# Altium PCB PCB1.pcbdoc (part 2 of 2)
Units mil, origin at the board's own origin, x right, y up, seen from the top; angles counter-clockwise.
Board outline 3120 x 2755.91 mil, 2 copper layers (Top Layer, Bottom Layer), stack 62.205 mil thick; 41 components, 124 nets, 614 pads, 395 vias.
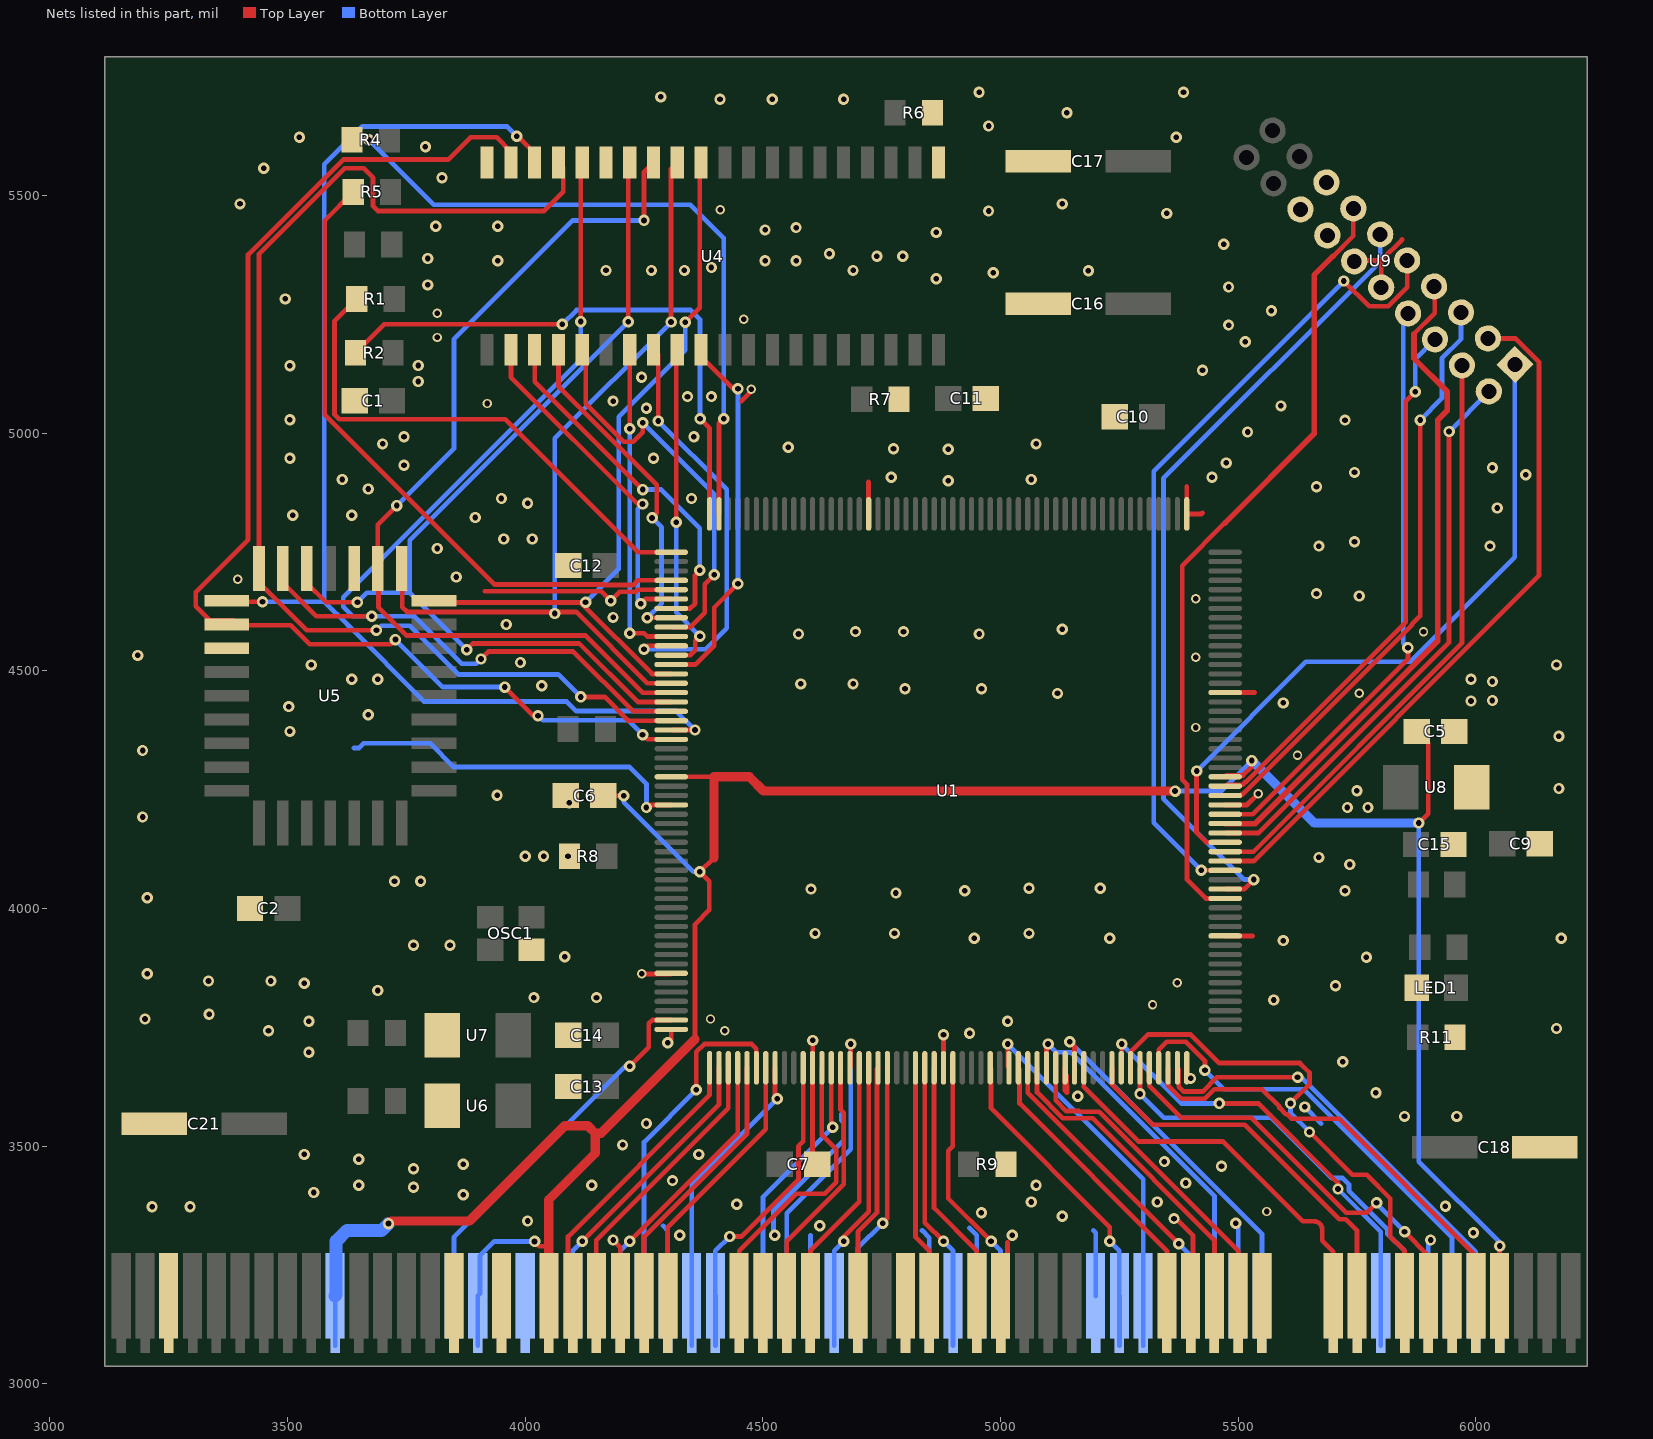
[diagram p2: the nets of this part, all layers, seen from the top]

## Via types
v1: diameter 23.62, hole 11.81, Top Layer to Bottom Layer, 223 vias
v2: diameter 24.02, hole 12.01, Top Layer to Bottom Layer, 148 vias
v3: diameter 19.68, hole 11.81, Top Layer to Bottom Layer, 20 vias
v4: diameter 23.62, hole 12.01, Top Layer to Bottom Layer, 3 vias
v5: diameter 39.37, hole 19.68, Top Layer to Bottom Layer, 1 vias

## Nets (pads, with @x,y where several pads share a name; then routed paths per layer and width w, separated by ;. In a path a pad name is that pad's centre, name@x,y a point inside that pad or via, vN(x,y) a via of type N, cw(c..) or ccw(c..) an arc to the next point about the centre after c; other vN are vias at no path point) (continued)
CASAL: R5.2 U1.160 | length 1375.1
  Top Layer w9.92: R5.2@3638.13,5507.68 3578.13,5447.68 3578.13,5039.47 3935.83,4681.77 4165.84,4681.77 4167.02,4680.59 4227.02,4680.59 4237.02,4690.59 U1.160@4307.32,4690.59
D0: U1.162 U4.2 | length 730.3
  Top Layer w9.92: U4.2@3970,5175.83 3970,5118.23 4237.02,4851.22 v2(4247.01,4851.22)
  Top Layer w10.24: v2(4242.96,4641.22) 4252.96,4651.22 U1.162@4307.32,4651.22
  Bottom Layer w9.92: v2(4242.96,4641.22) 4237.02,4647.16 4237.02,4841.22 v2(4247.01,4851.22)
D1: U1.163 U4.3 | length 759.2
  Top Layer w9.92: U4.3@4020,5175.83 4020,5108.86 v2(4247.33,4881.54) ; U1.163@4307.32,4631.54 4347.32,4631.54 4357.32,4641.54 4357.32,4701.54 v2(4367.32,4711.54)
  Bottom Layer w9.92: v2(4247.33,4881.54) 4286.14,4881.54 4367.32,4800.35 v2(4367.32,4711.54)
D2: U1.164 U4.4 | length 724.9
  Top Layer w9.92: U4.4@4070,5175.83 4070,5098.86 4277.01,4891.85 4277.01,4831.85 v2(4267.01,4821.85) ; v2(4257.01,4611.85) U1.164@4307.32,4611.85
  Bottom Layer w9.92: v2(4257.01,4611.85) 4287.01,4641.85 4287.01,4801.85 v2(4267.01,4821.85)
D3: U1.165 U4.5 | length 851.4
  Top Layer w9.92: U4.5@4120,5175.83 4127.64,5168.19 4127.64,5062.17 4207.64,4982.17 4227.64,4982.17 4247.64,5002.17 v2(4247.64,5022.17) ; U1.165@4307.32,4592.17 4347.64,4592.17 4377.64,4622.17 4377.64,4682.17 v2(4397.63,4702.17)
  Bottom Layer w9.92: v2(4247.64,5022.17) 4397.63,4872.17 v2(4397.63,4702.17)
D4: U1.166 U4.7 | length 686.6
  Top Layer w9.92: v2(4220,4579.49) 4250,4579.49 4257.01,4572.48 U1.166@4307.32,4572.48 ; v2(4220,5009.49) U4.7@4220,5175.83
  Bottom Layer w9.92: v2(4220,4579.49) v2(4220,5009.49)
D5: U1.167 U4.8 | length 902.3
  Top Layer w9.92: v2(4250,4545.79) 4257.01,4552.8 U1.167@4307.32,4552.8 ; U4.8@4270,5175.83 4280,5165.82 v2(4280,5025.78)
  Bottom Layer w9.92: v2(4250,4545.79) 4380,4545.79 4423.98,4589.76 4423.98,4881.81 v2(4280,5025.78)
D6: U1.168 U4.9 | length 713
  Top Layer w9.92: U1.168@4307.32,4533.11 4347.64,4533.11 4357.64,4543.11 4357.64,4563.11 v2(4367.64,4573.11) ; v2(4317.64,4813.11) 4317.64,5173.46 U4.9@4320,5175.83
  Bottom Layer w9.92: v2(4317.64,4813.11) 4317.64,4623.11 v2(4367.64,4573.11)
D7: U1.169 U4.10 | length 788
  Top Layer w9.92: U1.169@4307.32,4513.43 4357.64,4513.43 4397.63,4553.43 4397.63,4633.43 v2(4447.63,4683.43) ; U4.10@4370,5175.83 4377.64,5168.19 4377.64,5153.43 4437.63,5093.43 v2(4447.63,5093.43)
  Bottom Layer w9.92: v2(4447.63,4683.43) v2(4447.63,5093.43)
D8: U1.170 U4.31 U5.13 | length 1599.1
  Top Layer w9.92: U5.13@3807.92,4647.68 3811.86,4643.74 v2@4117.02,4643.74 ; v2(4127.02,4644.57) 4117.85,4644.57 v2@4117.02,4643.74 ; U1.170@4307.32,4493.74 4267.01,4493.74 v2@4117.02,4643.74 ; v2(4337.01,5233.73) 4367.01,5263.73 4367.01,5566.54 U4.31@4370,5569.53
  Bottom Layer w9.92: v2(4127.02,4644.57) 4197.02,4714.57 4197.02,5034.69 4337.01,5174.69 v2(4337.01,5233.73)
D9: U1.171 U4.32 U5.14 | length 1774.4
  Top Layer w9.92: U5.14@3740,4715.59 3741.53,4714.06 3741.53,4634.06 3751.53,4624.06 v2@4065.44,4624.06 ; v2@4067.02,4624.06 4107.02,4624.06 4257.01,4474.06 U1.171@4307.32,4474.06
  Top Layer w10: v2(4062.17,4620.78) 4065.44,4624.06 v2@4067.02,4624.06 ; v2(4307.01,5234.06) 4307.01,5556.54 U4.32@4320,5569.53
  Bottom Layer w10: v2(4062.17,4620.78) 4062.17,4989.21 v2(4307.01,5234.06)
D10: U1.172 U4.33 U5.15 | length 1954.4
  Top Layer w9.92: U5.15@3690,4715.59 3691.22,4714.37 3691.22,4634.37 3751.22,4574.37 4127.02,4574.37 4247.01,4454.37 U1.172@4307.32,4454.37
  Top Layer w10: U5.15@3690,4715.59 3690,4807.84 v2(3730,4847.84) ; v2(4249.99,5447.84) 4249.99,5549.52 U4.33@4270,5569.53
  Bottom Layer w10: v2(3730,4847.84) 3850,4967.84 3850,5197.84 4099.99,5447.84 v2(4249.99,5447.84)
D11: U1.173 U4.34 U5.18 | length 2025.2
  Top Layer w9.92: U5.18@3540,4715.59 3540.9,4714.69 3540.9,4684.69 3580.9,4644.69 v2(3647.02,4644.69) ; v2(3877.02,4544.69) 3890,4557.68 4114.03,4557.68 4237.02,4434.69 U1.173@4307.32,4434.69
  Top Layer w10: v2(4217.02,5234.69) 4217.02,5566.54 U4.34@4220,5569.53
  Bottom Layer w9.92: v2(3647.02,4644.69) 3667.02,4664.69 3757.02,4664.69 3765.66,4656.04 v2(3877.02,4544.69)
  Bottom Layer w10: 3757.02,4664.69 3757.02,4774.69 v2(4217.02,5234.69)
D12: U1.174 U4.36 U5.19 | length 2191.9
  Top Layer w9.92: U5.19@3490,4715.59 3490.59,4715 3490.59,4685 3560.59,4615 v2(3677.02,4615) ; v2(3907.02,4525) 3922.77,4540.75 4101.26,4540.75 4227.02,4415 U1.174@4307.32,4415
  Top Layer w10: v2(4117.02,5234.99) 4117.02,5566.54 U4.36@4120,5569.53
  Bottom Layer w9.92: v2(3677.02,4615) 3767.02,4615 3867.02,4515 3897.02,4515 v2(3907.02,4525)
  Bottom Layer w10: v2(3677.02,4615) 3637.02,4615 3617.02,4635 3617.02,4655 4117.02,5154.99 v2(4117.02,5234.99)
D13: U1.175 U4.37 U5.20 | length 2557.1
  Top Layer w9.92: U5.20@3440.27,4715.32 3440.27,4685.32 3540.27,4585.32 v2(3687.02,4585.32) ; v2(4117.02,4445.32) 4167.02,4445.32 4217.02,4395.32 U1.175@4307.32,4395.32
  Top Layer w10: U5.20@3440,4715.59 3440,5377.84 3620,5557.84 3660,5557.84 3680,5537.84 3680,5477.84 3690,5467.84 4039.99,5467.84 4079.99,5507.84 4079.99,5559.53 U4.37@4070,5569.53
  Bottom Layer w9.92: v2(3687.02,4585.32) 3697.02,4595.32 3757.02,4595.32 3859.66,4492.68 4069.66,4492.68 v2(4117.02,4445.32)
D14: U1.176 U4.38 U5.21 | length 2587
  Top Layer w9.92: U5.21@3372.09,4647.68 3374.14,4645.63 v2(3447.33,4645.63) ; U1.176@4307.32,4375.63 v2(4357.32,4375.63)
  Top Layer w10: v2(3982.33,5625) 3984.53,5625 4017.33,5592.2 4017.33,5572.2 U4.38@4020,5569.53
  Bottom Layer w9.92: v2(3447.33,4645.63) 3577.33,4645.63 3627.33,4595.63 3787.33,4435.63 4087.33,4435.63 4107.33,4415.63 4317.32,4415.63 v2(4357.32,4375.63)
  Bottom Layer w10: 3577.33,4645.63 3577.33,5565.62 3657.33,5645.62 3961.7,5645.62 v2(3982.33,5625)
D15: U1.177 U4.39 U5.22 | length 2619.3
  Top Layer w9.92: U5.22@3372.09,4597.68 3380.35,4605.95 3387.02,4605.95 3397.02,4595.95 3507.02,4595.95 3547.02,4555.95 3717.02,4555.95 v2(3727.02,4565.95) ; v2(3957.02,4465.95) 4017.02,4405.95 v2(4027.02,4405.95) ; v2(4247.01,4365.95) 4257.01,4355.95 U1.177@4307.32,4355.95
  Top Layer w10: U5.22@3387.02,4605.95 3337.02,4605.95 3307.02,4635.95 3307.02,4665.95 3417.02,4775.95 3417.02,5375.95 3617.02,5575.95 3838.27,5575.95 3885,5622.68 3940,5622.68 3970,5592.67 U4.39@3970,5569.53
  Bottom Layer w9.92: v2(3727.02,4565.95) 3827.02,4465.95 v2(3957.02,4465.95) ; v2(4027.02,4405.95) 4037.02,4395.95 4217.02,4395.95 v2(4247.01,4365.95)
DD0: ?.A58 U1.51 | length 1032.2
  Top Layer w9.92: U1.51@5372.28,3665 5375.15,3662.13 5375.15,3625 5385.15,3615 5425.15,3615 5455.15,3645 v2(5625.15,3645)
  Bottom Layer w9.92: v2(5625.15,3645) 5632.68,3645 6000.2,3277.48 ?.A58@6000.19,3185.04
  Bottom Layer w10: ?.A58@6000.19,3080.31 ?.A58@6000.19,3185.04
DD1: ?.B58 U1.50 | length 1040.8
  Top Layer w9.92: U1.50@5352.6,3665 5352.6,3627.55 5380.2,3599.96 5430.2,3599.96 5450.2,3619.96 5550.2,3619.96 5587.24,3582.91 5587.24,3580.45 5600.69,3567.01 5603.15,3567.01 5612.48,3557.68 5712.48,3557.68 6000.2,3269.96 ?.B58@6000.19,3185.04
  Top Layer w10: ?.B58@6000.19,3080.31 ?.B58@6000.19,3185.04
DD2: ?.A57 U1.49 | length 1071.9
  Top Layer w9.92: U1.49@5332.91,3665 5332.91,3702.67 5350.2,3719.96 5390.2,3719.96 5430.2,3679.96 v2(5430.2,3659.96)
  Bottom Layer w9.92: v2(5430.2,3659.96) 5470.2,3619.96 5637.72,3619.96 5950.2,3307.48 ?.A57@5950.19,3185.04
  Bottom Layer w10: ?.A57@5950.19,3080.31 ?.A57@5950.19,3185.04
DD3: ?.B56 U1.48 | length 981.3
  Top Layer w9.92: U1.48@5313.23,3665 5313.23,3626.92 5380.2,3559.96 5527.72,3559.96 5727.72,3359.96 5770.2,3359.96 v2(5791.27,3381.04) ; v2(5850.2,3319.96) 5900.2,3269.96 ?.B56@5900.19,3185.04
  Top Layer w10: ?.B56@5900.19,3080.31 ?.B56@5900.19,3185.04
  Bottom Layer w9.92: v2(5791.27,3381.04) 5791.27,3378.88 v2(5850.2,3319.96)
DD4: ?.A55 U1.47 | length 961.2
  Top Layer w9.92: v2(5293.54,3609.96) U1.47@5293.54,3665
  Bottom Layer w9.92: v2(5293.54,3609.96) 5343.54,3559.96 5570.2,3559.96 5697.25,3432.9 5719.69,3432.9 5733.14,3419.46 5733.14,3406.71 5814.13,3325.71 5814.13,3316.02 5850.2,3279.96 ?.A55@5850.19,3185.04
  Bottom Layer w10: ?.A55@5850.19,3080.31 ?.A55@5850.19,3185.04
DD5: ?.B55 U1.46 | length 1166.4
  Top Layer w9.92: U1.46@5273.86,3665 5273.86,3698.67 5310.2,3735 5400.2,3735 5460.2,3675 5630.2,3675 5650.2,3655 5650.2,3629.96 v2(5610.2,3589.96) ; v2(5650.2,3529.96) 5740.2,3439.96 5770.2,3439.96 5820.2,3389.96 5820.2,3309.96 5850.2,3279.96 ?.B55@5850.19,3185.04
  Top Layer w10: ?.B55@5850.19,3080.31 ?.B55@5850.19,3185.04
  Bottom Layer w9.92: v2(5610.2,3589.96) 5610.2,3569.96 v2(5650.2,3529.96)
DD6: ?.A54 U1.45 | length 1006.1
  Top Layer w9.92: U1.45@5254.17,3665 5255.15,3665.99 v2(5255.15,3715) ; v2(5460.2,3589.96) 5542.72,3589.96 5710.19,3422.49 v2(5710.19,3409.95)
  Bottom Layer w9.92: v2(5255.15,3715) 5380.2,3589.96 v2(5460.2,3589.96) ; v2(5710.19,3409.95) 5800.2,3319.94 ?.A54@5800.19,3185.04
  Bottom Layer w10: ?.A54@5800.19,3080.31 ?.A54@5800.19,3185.04
DD7: ?.B53 U1.44 | length 919.8
  Top Layer w9.92: U1.44@5234.49,3665 5234.49,3630.74 5320.2,3545.04 5513.61,3545.04 5712.62,3346.02 5726.66,3346.02 5750.2,3322.48 ?.B53@5750.19,3185.04
  Top Layer w10: ?.B53@5750.19,3080.31 ?.B53@5750.19,3185.04
DD8: ?.B52 U1.41 | length 922.9
  Top Layer w9.92: U1.41@5175.43,3665 5175.43,3624.73 5290.2,3509.96 5467.72,3509.96 5635.71,3341.97 5660.04,3341.97 cw(c5660.04,3325.2) 5676.81,3325.2 5676.81,3300.87 5700.2,3277.48 ?.B52@5700.19,3185.04 ?.B52@5700.19,3080.31
DD9: ?.A49 U1.40 | length 866.3
  Top Layer w9.92: v2(5145.75,3719.96) 5155.75,3709.96 U1.40@5155.75,3665
  Bottom Layer w9.92: v2(5145.75,3719.96) 5550.2,3315.51 ?.A49@5550.2,3185.04
  Bottom Layer w10: ?.A49@5550.2,3080.31 ?.A49@5550.2,3185.04
DD10: ?.B48 U1.38 | length 783.2
  Top Layer w9.92: U1.38@5116.38,3665 5116.38,3596.29 5138.78,3573.9 5165.97,3573.9 5167.19,3572.68 5207.48,3572.68 5500.2,3279.96 ?.B48@5500.2,3185.04
  Top Layer w10: ?.B48@5500.2,3080.31 ?.B48@5500.2,3185.04
DD11: ?.A47 U1.37 | length 849.2
  Top Layer w9.92: U1.37@5096.69,3665 5096.69,3711.49 v2(5100.2,3715)
  Bottom Layer w9.92: v2(5100.2,3715) 5117.52,3697.68 5135.57,3697.68 5136.24,3697.01 5149,3697.01 5450.2,3395.8 ?.A47@5450.2,3185.04
  Bottom Layer w10: ?.A47@5450.2,3080.31 ?.A47@5450.2,3185.04
DD12: ?.B47 U1.36 | length 775.9
  Top Layer w9.92: U1.36@5077.01,3665 5077.01,3613.14 5131.42,3558.74 5193.94,3558.74 5450.2,3302.48 ?.B47@5450.2,3185.04
  Top Layer w10: ?.B47@5450.2,3080.31 ?.B47@5450.2,3185.04
DD13: ?.A46 U1.35 | length 726.7
  Top Layer w9.92: U1.35@5057.32,3665 5057.32,3612.84 v2(5375.2,3294.96)
  Bottom Layer w9.92: v2(5375.2,3294.96) 5400.2,3269.96 ?.A46@5400.2,3185.04
  Bottom Layer w10: ?.A46@5400.2,3080.31 ?.A46@5400.2,3185.04
DD14: ?.B45 U1.34 | length 714.2
  Top Layer w9.92: U1.34@5037.64,3665 5040.2,3662.45 5040.2,3589.96 5350.2,3279.96 ?.B45@5350.2,3185.04
  Top Layer w10: ?.B45@5350.2,3080.31 ?.B45@5350.2,3185.04
DD15: ?.A44 U1.33 | length 803.8
  Top Layer w9.92: v2(5015.24,3715) 5015.24,3667.71 U1.33@5017.95,3665
  Bottom Layer w9.92: v2(5015.24,3715) 5300.2,3430.04 ?.A44@5300.2,3185.04
  Bottom Layer w10: ?.A44@5300.2,3080.31 ?.A44@5300.2,3185.04
DD16: ?.A32 U1.20 | length 610.3
  Top Layer w9.92: v2(4752.05,3338.1) 4762.05,3348.1 U1.20@4762.05,3665
  Bottom Layer w9.92: ?.A32@4700.2,3185.04 4700.2,3286.25 v2(4752.05,3338.1)
  Bottom Layer w10: ?.A32@4700.2,3080.31 ?.A32@4700.2,3185.04
DD17: ?.B32 U1.19 | length 602.2
  Top Layer w9.92: ?.B32@4700.2,3185.04 4700.2,3319.96 4740.2,3359.96 4740.2,3662.84 U1.19@4742.36,3665
  Top Layer w10: ?.B32@4700.2,3080.31 ?.B32@4700.2,3185.04
DD18: ?.A31 U1.18 | length 614.7
  Top Layer w9.92: v2(4670.2,3299.96) 4670.2,3309.96 4722.68,3362.44 U1.18@4722.68,3665
  Bottom Layer w9.92: ?.A31@4650.2,3185.04 4650.2,3279.96 v2(4670.2,3299.96)
  Bottom Layer w10: ?.A31@4650.2,3080.31 ?.A31@4650.2,3185.04
DD19: ?.B30 U1.17 | length 627.3
  Top Layer w9.92: ?.B30@4600.2,3185.04 4600.2,3279.96 4702.99,3382.75 U1.17@4702.99,3665
  Top Layer w10: ?.B30@4600.2,3080.31 ?.B30@4600.2,3185.04
DD20: ?.A29 U1.16 | length 741.4
  Top Layer w9.92: U1.16@4683.31,3665 4685.16,3666.84 v2(4685.16,3715)
  Bottom Layer w9.92: ?.A29@4550.2,3185.04 4550.2,3358.7 4685.16,3493.66 v2(4685.16,3715)
  Bottom Layer w10: ?.A29@4550.2,3080.31 ?.A29@4550.2,3185.04
DD21: ?.B29 U1.15 | length 637.1
  Top Layer w9.92: ?.B29@4550.2,3185.04 4550.2,3299.96 4670.2,3419.96 4670.2,3569.96 4663.62,3576.54 U1.15@4663.62,3665
  Top Layer w10: ?.B29@4550.2,3080.31 ?.B29@4550.2,3185.04
DD22: ?.A28 U1.14 | length 646.9
  Top Layer w9.92: U1.14@4643.94,3665 4643.94,3543.22 v2(4647.2,3539.96)
  Bottom Layer w9.92: ?.A28@4500.2,3185.04 4500.2,3392.95 v2(4647.2,3539.96)
  Bottom Layer w10: ?.A28@4500.2,3080.31 ?.A28@4500.2,3185.04
DD23: ?.B27 U1.13 | length 716.8
  Top Layer w9.92: ?.B27@4450.2,3185.04 4450.2,3279.96 4570.2,3399.96 4630.2,3399.96 4654.25,3424.01 4654.25,3494.01 4624.25,3524.01 U1.13@4624.25,3665
  Top Layer w10: ?.B27@4450.2,3080.31 ?.B27@4450.2,3185.04
DD24: ?.A25 U1.8 | length 661.1
  Top Layer w9.92: U1.8@4525.83,3665 4525.83,3604.32 v2(4530.2,3599.96)
  Bottom Layer w9.92: ?.A25@4350.2,3185.04 4350.2,3419.96 v2(4530.2,3599.96)
  Bottom Layer w10: ?.A25@4350.2,3080.31 ?.A25@4350.2,3185.04
DD25: ?.B24 U1.7 | length 670
  Top Layer w9.92: ?.B24@4300.2,3185.04 4300.2,3329.96 4506.14,3535.9 U1.7@4506.14,3665
  Top Layer w10: ?.B24@4300.2,3080.31 ?.B24@4300.2,3185.04
DD26: ?.A23 U1.6 | length 841.1
  Top Layer w9.92: v2(4360.2,3618.74) 4360.2,3698.74 4376.46,3715 4476.46,3715 4486.46,3705 U1.6@4486.46,3665
  Bottom Layer w9.92: ?.A23@4250.2,3185.04 4250.2,3508.74 v2(4360.2,3618.74)
  Bottom Layer w10: ?.A23@4250.2,3080.31 ?.A23@4250.2,3185.04
DD27: ?.B23 U1.5 | length 674.4
  Top Layer w9.92: ?.B23@4250.2,3185.04 4250.2,3309.96 4466.77,3526.53 U1.5@4466.77,3665
  Top Layer w10: ?.B23@4250.2,3080.31 ?.B23@4250.2,3185.04
DD28: ?.A22 U1.4 | length 687
  Top Layer w9.92: v2(4220.2,3299.96) 4447.09,3526.85 U1.4@4447.09,3665
  Bottom Layer w9.92: ?.A22@4200.2,3185.04 4200.2,3279.96 v2(4220.2,3299.96)
  Bottom Layer w10: ?.A22@4200.2,3080.31 ?.A22@4200.2,3185.04
DD29: ?.B21 U1.3 | length 699.7
  Top Layer w9.92: ?.B21@4149.8,3185.04 4149.81,3302.48 4427.4,3580.08 U1.3@4427.4,3665
  Top Layer w10: ?.B21@4149.8,3080.31 ?.B21@4149.8,3185.04
DD30: ?.A20 U1.2 | length 712.1
  Top Layer w9.92: v2(4120.2,3299.96) 4407.72,3587.48 U1.2@4407.72,3665
  Bottom Layer w9.92: ?.A20@4100.2,3185.04 4100.2,3279.96 v2(4120.2,3299.96)
  Bottom Layer w10: ?.A20@4100.2,3080.31 ?.A20@4100.2,3185.04
DD31: ?.B20 U1.1 | length 712.2
  Top Layer w9.92: ?.B20@4100.2,3185.04 4090.2,3195.04 4090.2,3309.96 4388.03,3607.79 U1.1@4388.03,3665
  Top Layer w10: ?.B20@4100.2,3080.31 ?.B20@4100.2,3185.04
FLM: U1.67 U9.13 | length 1661.9
  Top Layer w9.84: 5700,5372.68 5742.39,5415.06 U9.13@5742.39,5473.04
  Top Layer w9.92: 5472.37,4811.29 5382.37,4721.29 5382.37,4271.3 5392.37,4261.3 5392.37,4061.3 5432.37,4021.3 U1.67@5472.68,4021.3
  Top Layer w11.81: 5472.37,4811.29 5660,4998.93 5660,5332.68 5700,5372.68
GND: ?.A18 ?.A24 ?.A30 ?.A35 ?.A37 ?.A42 ?.A48 ?.A56 ?.B3 ?.B15 ?.B17 ?.B22 ?.B28 ?.B34 ?.B38 ?.B46 ?.B49 ?.B57 C1.1 C2.1 C5.1 C6.1 C7.1 C9.1 C10.1 C11.1 C12.1 C13.1 C14.1 C15.1 C16.2 C17.2 C18.2 C21.2 LED1.2 OSC1.2 R6.2 R7.2 R8.2 R9.2 R11.1 U1.12 U1.26 U1.39 U1.52 U1.63 U1.77 U1.89 U1.105 U1.139 U1.161 U1.184 U1.202 U1.208 U4.21 U4.35 U4.40 U5.16 U5.23 U6.2 U7.2 U8.2 U9.10 U9.12 U9.14 U9.15 U9.16 | length 4042.2
  Top Layer w9.92: v1(4185,3302.68) 4200.2,3287.48 ?.B22@4200.2,3185.04 ; 4455,5067.68 4475.47,5088.15 v3(4475.47,5092.68) ; ?.B38@5000.2,3185.04 5015,3199.84 5015,3297.68 ; v1(5365,3347.68) 5370,3347.68 5405,3312.68 5405,3189.84 ?.B46@5400.2,3185.04 ; U9.12@5744.33,5361.71 5746.27,5363.65 5800.97,5363.65 ; U9.10@5800.97,5307.01 5800.97,5363.65 ; 5845,5407.68 5800.97,5363.65
  Top Layer w10.24: 3915,4667.68 4160,4667.68 v1(4180,4647.68) 4198.81,4666.49 4232.85,4666.49 4237.27,4670.91 U1.161@4307.32,4670.91 ; v3(4245,3862.68) 4306.18,3862.68 U1.202@4307.32,3863.82 ; v1(4255,4212.68) 4260.47,4218.15 U1.184@4307.32,4218.15 ; v1(4300,3717.68) 4307.32,3725 U1.208@4307.32,3745.71 ; v1@4605,3723.34 v1(4605,3722.68) 4605,3665.43 U1.12@4604.57,3665 4604.57,3471.52 C7.1@4614.26,3461.83 ; U1.139@4722.68,4830.35 4722.68,4897.68 ; U1.26@4880.16,3665 v1(4880.16,3734.27) ; U1.39@5136.06,3665 U1.39@5136.06,3651.57 ; 5391.97,4887.68 U1.105@5391.97,4830.35 5422.68,4830.35 5425,4832.68 ; U1.63@5472.68,3942.56 5530,3942.56 ; U1.77@5472.68,4218.15 5518.65,4218.15 v3(5542.27,4241.77) ; U1.89@5472.68,4454.37 5535,4454.37 ; U1.39@5136.06,3651.57 5139.14,3648.49 5139.14,3628.2 5140,3627.33 5140,3612.68 5136.06,3616.62 U1.39@5136.06,3651.57
  Bottom Layer w9.92: 4290,3332.68 4300.2,3322.48 ?.A24@4300.2,3185.04 ; v1(4525,3312.68) 4522.5,3315.18 4522.5,3365.18 4670,3512.68 4670,3530.3 4670.16,3530.45 4670.16,3549.47 4665,3554.62 4665,3567.68 ; ?.A30@4600.2,3185.04 4600.2,3312.68 ; 4835,3322.68 4850.2,3307.48 ?.A35@4850.2,3185.04 ; 4935,3327.68 4950.2,3312.48 ?.A37@4950.2,3185.04 ; 5195,3322.68 5200.2,3317.48 ?.A42@5200.2,3185.04 ; v1(5495,3337.68) 5500.2,3332.48 ?.A48@5500.2,3185.04 ; v1(5640,3582.68) 5675,3547.68 ; ?.A56@5900.19,3185.04 5900.19,3297.87 v1(5905,3302.68)
  Bottom Layer w10.24: 3640,4337.68 3650,4337.68 3660,4347.68 3800,4347.68 3850,4297.68 4220,4297.68 4255,4262.68 v1(4255,4212.68)
  other v1: 4325,3312.68 5025,3312.68 5995,3317.68 4620,3332.68 4005,3342.68 5130,3352.68 4959.89,3359.96 3215,3372.68 3295,3372.68 5936.09,3373.77 4445,3377.68 5065,3382.68 5330,3382.68 3869.75,3397.76 3555,3402.68 3765,3413.59 3650,3417.68 4140,3417.68 5075,3417.68 5390,3422.68 4310,3427.68 3765,3452.68 5465,3457.68 3869.75,3461.83 5345,3467.68 3650,3472.68 3535,3482.68 4365,3482.68 4205,3502.68 4255,3547.68 5850,3562.68 5960,3562.68 5162.65,3605.33 5790,3612.68 5400,3642.68 5720,3677.68 3545,3697.68 4935,3737.68 3460,3742.68 6170,3747.68 3545,3762.68 5015,3762.68 3200,3767.68 3335,3777.68 5575,3807.68 4018.27,3812.68 4150,3812.68 3690,3827.68 5705,3837.68 3535,3842.68 3333.77,3847.68 3465,3847.68 3205,3862.68 5770,3897.68 4083.49,3898.5 3765,3922.68 3841.8,3922.68 5595,3932.68 4945,3937.68 5230,3937.68 6180,3937.68 4610,3947.68 4777.14,3947.68 5060,3947.68 3205,4022.68 4780,4032.68 4925,4037.68 5725,4037.68 4601.38,4040.99 5060,4042.68 5210,4042.68 3725,4057.68 3780,4057.68 5735,4092.68 5670,4107.68 4000.05,4110.11 4038.77,4110.11 4090.01,4110.11 3195,4192.68 5730,4212.68 5773.08,4212.68 4092.58,4222.68 3940.93,4238.42 5750,4247.68 6175,4252.68 3195,4332.68 6175,4362.68 3505,4372.68 3670,4407.68 3502.64,4424.89 5595,4432.68 5990,4436.8 6035,4437.68 5120,4452.68 4799.12,4462.68 4960,4462.68 4035,4468.8 4580,4472.68 4690,4472.68 6035,4477.68 3635,4482.68 3690,4482.68 5990,4482.68 3550,4512.68 6170,4512.68 3990,4517.68 3185,4532.68 4575,4577.68 4955,4577.68 4695,4582.68 4795.98,4582.68 5130,4587.68 3960,4597.68 4185,4612.68 5755,4657.68 5665,4662.68 3855,4697.68 3815,4757.68 5670,4762.68 6030,4762.68 5745,4771.58 3955,4777.68 4015,4777.68 3895,4822.68 3510.97,4827.68 3635,4827.68 6045,4842.68 4005,4852.68 3950,4862.68 4350,4862.68 3670,4882.68 5665,4887.68 4890,4900.27 3615,4902.68 5065,4902.68 4770,4907.68 5445,4907.68 6105,4912.68 5745,4917.68 6035,4927.68 3745,4932.68 5475,4937.68 3505,4947.68 4270,4947.68 4890,4966.18 4775,4967.68 4553.28,4970.66 3700,4977.68 5075,4977.68 3745,4992.68 4355,4992.68 5520,5002.68 3505,5028.23 5725,5027.68 4255,5052.68 5590,5057.68 4185,5067.68 4341.41,5077.23 4391.73,5077.23 3775,5109.03 4245,5117.68 5425,5132.68 3505,5142.18 3775,5142.68 5515,5192.68 5480,5227.68 5570,5257.68 3495,5282.68 5480,5307.68 3795,5312.16 4865,5325.24 4985,5337.68 5185,5342.05 4170,5342.68 4265.62,5342.68 4335,5342.68 4690,5342.68 4391.73,5348.88 3942.46,5363.03 4504.72,5363.03 4570,5363.03 3795,5367.68 4740,5372.68 4794.25,5372.68 4640,5377.68 5470,5397.68 4865,5422.68 4504.72,5427.97 4570,5432.68 3811.71,5435.45 3942.46,5435.45 5350,5462.68 4975,5467.68 3400,5482.68 5130,5482.68 3825,5537.68 3450,5557.68 3790,5602.68 3525,5622.68 5370,5622.68 4975,5646.52 5139.82,5674.31 4410,5702.68 4520,5702.68 4670,5702.68 4285,5707.68 4955,5717.68 5385,5717.68
  other v3: 5560,3362.68 4420,3742.68 4390,3767.68 5320,3797.68 5371.96,3844.14 5625,4322.68 5410.74,4380.99 5755,4452.68 5410.74,4528.78 5890,4582.68 5410.74,4651.86 3395,4692.68 3920,5062.68 3815,5201.64 4460,5239.97 3815,5252.68 4410.55,5469.95
IVCC: ?.A10 ?.A16 ?.A59 ?.B19 ?.B59 C5.2 C6.2 U1.80 U1.181 | length 6198.2
  Top Layer w9.92: C6.2@4174.37,4222.68 4189.07,4237.38 v2(4207.24,4237.38) ; U1.181@4307.32,4277.21 4397.41,4277.21 ; v2(4367.41,4077.21) 4397.41,4107.21 ; U1.80@5472.68,4277.21 5475.46,4280 5510.2,4280 5528.82,4298.62 v2(5528.82,4311.37)
  Top Layer w10: v2(4019.81,3299.6) 4029.81,3289.6 4049.81,3289.6 ; ?.B19@4049.8,3080.31 ?.B19@4049.8,3185.04 ; 4357.41,3725.09 4357.41,3967.21 4387.41,3997.21 4387.41,4057.21 v2(4367.41,4077.21) ; C5.2@5875.63,4372.68 5900.2,4348.11 5900.2,4200 v2(5880.2,4180) ; ?.B59@6050.19,3080.31 ?.B59@6050.19,3185.04 v2(6050.2,3290)
  Top Layer w19.68: v2(3712.41,3337.21) 3717.88,3342.68 3882.88,3342.68 4082.88,3542.68 4131.95,3542.68 4147.41,3527.21 ; ?.B19@4049.8,3185.04 4049.81,3289.6 4049.81,3387.48 4147.41,3485.09 4147.41,3527.21 ; 4357.41,3725.09 4159.53,3527.21 4147.41,3527.21 ; 4397.41,4107.21 4397.41,4277.21 4471.27,4277.21 4501.27,4247.21 v2(5367.41,4247.21)
  Bottom Layer w9.92: v2(4207.24,4237.38) 4207.24,4223.97 4354.01,4077.21 v2(4367.41,4077.21) ; v2(5367.41,4247.21) 5464.66,4247.21 v2(5528.82,4311.37)
  Bottom Layer w10: ?.A10@3600.2,3080.31 ?.A10@3600.2,3185.04 ; ?.A16@3900.2,3080.31 ?.A16@3900.2,3185.04 3904.77,3189.6 3904.77,3269.6 3934.77,3299.6 v2(4019.81,3299.6) ; v2(5880.2,4180) 5880.2,3467.48 6050.2,3297.48 v2(6050.2,3290) ?.A59@6050.19,3185.04 ?.A59@6050.19,3080.31
  Bottom Layer w19.68: v2(5528.82,4311.37) 5660.2,4180 v2(5880.2,4180)
  Bottom Layer w27.56: ?.A10@3600.2,3185.04 3602.37,3187.21 3602.37,3300.05 3625,3322.68 3697.88,3322.68 v2(3712.41,3337.21)
LCLK: ?.A38 U1.27 | length 634.2
  Top Layer w9.92: U1.27@4899.84,3665 4899.84,3499.6 4890.2,3489.96 4890.2,3389.96 v2(4980.2,3299.96)
  Bottom Layer w9.92: v2(4980.2,3299.96) 5000.2,3279.96 ?.A38@5000.2,3185.04
  Bottom Layer w10: ?.A38@5000.2,3080.31 ?.A38@5000.2,3185.04
LDEV: ?.B37 U1.25 | length 621.7
  Top Layer w9.92: U1.25@4860.2,3664.73 4860.2,3369.96 4950.2,3279.96 ?.B37@4950.2,3185.04
  Top Layer w10: ?.B37@4950.2,3080.31 ?.B37@4950.2,3185.04
LP: U1.68 U9.11 | length 1705.3
  Top Layer w9.92: U1.68@5472.68,4040.99 5512.99,4040.99 v2(5532.99,4060.99)
  Bottom Layer w9.92: v2(5532.99,4060.99) 5512.99,4060.99 5342.99,4230.99 5342.99,4904.95 5799.03,5360.99 U9.11@5799.03,5418.35
LRDY: ?.A36 U1.24 | length 609.3
  Top Layer w9.92: U1.24@4840.79,3665 4840.79,3339.36 v2(4880.2,3299.96)
  Bottom Layer w9.92: v2(4880.2,3299.96) 4900.2,3279.96 ?.A36@4900.2,3185.04
  Bottom Layer w10: ?.A36@4900.2,3080.31 ?.A36@4900.2,3185.04
M/IO: ?.A43 U1.31 | length 697.2
  Top Layer w9.92: U1.31@4978.58,3665 4980.2,3663.38 4980.2,3579.96 5230.2,3329.96 v2(5230.2,3299.96)
  Bottom Layer w9.92: v2(5230.2,3299.96) 5250.2,3279.96 ?.A43@5250.2,3185.04
  Bottom Layer w10: ?.A43@5250.2,3080.31 ?.A43@5250.2,3185.04
OEAB: R4.2 U1.155 | length 1452.3
  Top Layer w9.92: R4.2@3635.63,5617.68 v2(3670.71,5617.68) ; U1.155@4407.72,4830.35 4407.72,5020.66 v2(4417.72,5030.66)
  Bottom Layer w9.92: v2(3670.71,5617.68) 3807.72,5480.66 4347.72,5480.66 4417.72,5410.66 v2(4417.72,5030.66)
P0: U1.71 U9.3 | length 1486.7
  Top Layer w9.92: U1.71@5472.68,4100.04 5532.99,4100.04 6132.99,4700.03 6132.99,5150.03 6083.47,5199.55 U9.3@6025.59,5199.56
P1: U1.72 U9.4 | length 1264.5
  Top Layer w9.92: U1.72@5472.68,4119.73 5532.37,4119.73 5970.89,4558.26 U9.4@5970.89,5142.92
P2: U1.73 U9.1 | length 1459.9
  Top Layer w9.92: v2(5412.68,4289.41) 5412.68,4159.41 5432.68,4139.41 U1.73@5472.68,4139.41
  Bottom Layer w9.92: v2(5412.68,4289.41) 5642.68,4519.4 5862.68,4519.4 6082.23,4738.96 U9.1@6082.23,5144.86
P3: U1.74 U9.2 | length 1200.1
  Top Layer w9.92: U1.74@5472.68,4159.1 5542.99,4159.1 5943.9,4560.01 v2(5943.9,5003.67)
  Bottom Layer w9.92: v2(5943.9,5003.67) 6027.53,5087.3 U9.2@6027.54,5088.22
P4: U1.75 U9.7 | length 1408.6
  Top Layer w9.84: 5870,5208.91 5913.72,5252.63 5913.72,5307.54 U9.7@5912.31,5308.95
  Top Layer w11.81: U1.75@5472.68,4178.78 5536.1,4178.78 5920,4562.68 5920,5027.68 5940,5047.68 5940,5087.68 5870,5157.68 5870,5208.91
P5: U1.76 U9.8 | length 1255.4
  Top Layer w9.92: U1.76@5472.68,4198.47 5530.79,4198.47 5857.3,4524.98 v2(5857.3,4548.78)
  Bottom Layer w9.92: v2(5857.3,4548.78) 5847.61,4558.47 5847.61,5242.31 U9.8@5857.61,5252.31
P6: U1.78 U9.5 | length 1242.4
  Top Layer w9.92: U1.78@5472.68,4237.84 5505.16,4237.84 5508.38,4241.06 5510.68,4241.06 5866.61,4596.99 5866.61,4599.29 5882.99,4615.66 v2(5882.99,5027.84)
  Bottom Layer w9.92: v2(5882.99,5027.84) 5928.95,5073.8 5928.95,5157.84 5968.95,5197.84 U9.5@5968.95,5254.25
P7: U1.79 U9.6 | length 1143.4
  Top Layer w9.92: U1.79@5472.68,4257.52 5475.91,4260.75 5509.41,4260.75 5514.72,4266.06 5515.97,4266.06 5852.68,4602.77 5852.68,5067.51 v2(5872.68,5087.51)
  Bottom Layer w9.92: v2(5872.68,5087.51) 5872.68,5156.03 U9.6@5914.25,5197.61
RASA: R2.1 U1.156 | length 1187.7
  Top Layer w9.92: R2.1@3643.13,5169.31 3703.13,5229.31 v2(4078.03,5229.31) ; v2(4368.03,5030.66) 4388.03,5010.66 U1.156@4388.03,4830.35
  Bottom Layer w9.92: v2(4078.03,5229.31) 4108.03,5259.31 4348.03,5259.31 4368.03,5239.31 v2(4368.03,5030.66)
RDYRTN: ?.B35 U1.23 | length 596.7
  Top Layer w9.92: U1.23@4821.1,3665 4821.1,3309.06 4850.2,3279.96 ?.B35@4850.2,3185.04
  Top Layer w10: ?.B35@4850.2,3080.31 ?.B35@4850.2,3185.04
RST: ?.A15 U1.207 | length 903.7
  Top Layer w9.92: v2(4220.2,3668.27) 4260.2,3708.27 4260.2,3758.27 4267.32,3765.4 U1.207@4307.32,3765.4
  Bottom Layer w9.92: ?.A15@3850.2,3185.04 3850.2,3308.27 4210.2,3668.27 v2(4220.2,3668.27)
  Bottom Layer w10: ?.A15@3850.2,3080.31 ?.A15@3850.2,3185.04
SHFCLK: U1.70 U9.9 | length 1726
  Top Layer w9.92: v2(5422.37,4080.36) U1.70@5472.68,4080.36 ; v2(5722.37,5320.36) 5775.67,5267.05 5815.67,5267.05 5855.67,5307.05 U9.9@5855.67,5363.65
  Bottom Layer w9.92: v2(5422.37,4080.36) 5322.37,4180.36 5322.37,4920.36 v2(5722.37,5320.36)
W/R: ?.A26 U1.11 | length 675.6
  Top Layer w9.92: v2(4430.2,3309.96) 4454.88,3309.96 4574.88,3429.96 4574.88,3499.96 4584.88,3509.96 U1.11@4584.88,3665
  Bottom Layer w9.92: ?.A26@4400.2,3185.04 4400.2,3279.96 v2(4430.2,3309.96)
  Bottom Layer w10: ?.A26@4400.2,3080.31 ?.A26@4400.2,3185.04
WEA: R1.1 U1.157 | length 1091.3
  Top Layer w9.92: R1.1@3645.63,5282.68 3598.66,5235.7 3598.66,5039.65 3608.66,5029.65 3958.03,5029.65 4238.03,4749.65 U1.157@4307.32,4749.65
pads on no net: ?.A1 ?.A3 ?.A4 ?.A6 ?.A7 ?.A9 ?.A11 ?.A12 ?.A13 ?.A14 ?.A17 ?.A19 ?.A21 ?.A27 ?.A33 ?.A39 ?.A40 ?.A41 ?.A45 ?.A53 ?.A60 ?.B1 ?.B2 ?.B4 ?.B7 ?.B8 ?.B9 ?.B10 ?.B11 ?.B12 ?.B13 ?.B14 ?.B18 ?.B25 ?.B31 ?.B36 ?.B39 ?.B41 ?.B43 ?.B54 ?.B60 OSC1.1 U1.54 U1.56 U1.57 U1.58 U1.60 U1.61 U1.62 U1.64 U1.65 U1.69 U1.81 U1.82 U1.83 U1.84 U1.85 U1.86 U1.87 U1.88 U1.90 U1.91 U1.92 U1.93 U1.94 U1.95 U1.96 U1.97 U1.98 U1.99 U1.100 U1.101 U1.102 U1.103 U1.104 U1.106 U1.107 U1.109 U1.110 U1.111 U1.112 U1.113 U1.114 U1.115 U1.116 U1.117 U1.118 U1.119 U1.120 U1.121 U1.122 U1.123 U1.124 U1.125 U1.126 U1.127 U1.128 U1.129 U1.130 U1.131 U1.132 U1.133 U1.134 U1.135 U1.136 U1.137 U1.138 U1.140 U1.141 U1.143 U1.144 U1.154 U1.197 U1.198 U1.204 U4.6 U4.11 U4.12 U4.15 U4.30 U5.1 U5.12 U5.17 U5.26

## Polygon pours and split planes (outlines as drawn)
GND on Top Layer (solid, remove dead copper, pour order 0): 3808.98,4366.83 4055,4366.83 4055,4142.68 3808.98,4142.68
no net on Bottom Layer (solid, remove dead copper, pour order 4): 3000,5917.68 3010,5917.68 3010,5907.68 3000,5907.68
GND on Bottom Layer (solid, remove dead copper, pour order 6): 4855,3947.68 6195,3947.68 6195,3292.68 4855,3292.68
GND on Bottom Layer (solid, remove dead copper, pour order 8): 3005,5867.68 6285,5867.68 6285,3132.68 3005,3132.68
GND on Top Layer (solid, remove dead copper, pour order 2): 3025,5872.68 6280,5872.68 6280,3127.68 3025,3127.68

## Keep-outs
Board Outline Layer:
  the board outline again, w10

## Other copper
Top Layer:
  text "LCL-EL LCD" at 3350,4802.68 h157.48 r90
